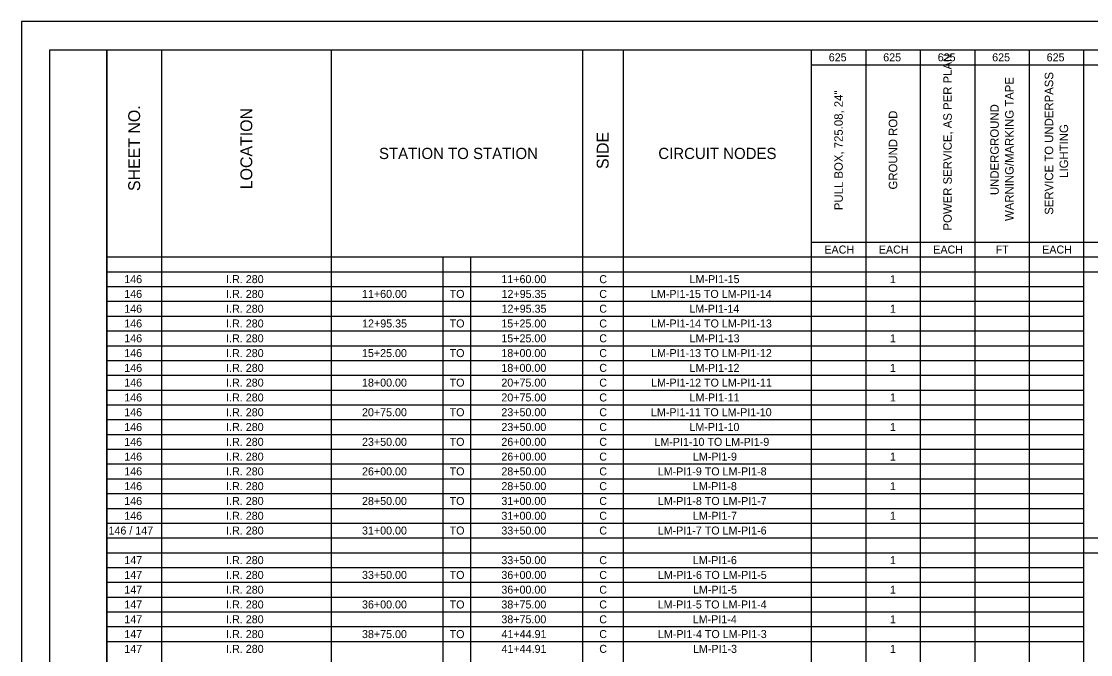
# Model space of a CAD drawing. Extents: x 0 to 34, y 0 to 22.
# Drawn here: x 0 to 18.75, y 10.9 to 22 of the extents above; entities that cross this region are included whole.
import ezdxf

# ---------------------------------------------------------------- set-up
doc = ezdxf.new("R2010")
doc.units = 0
for name, color, linetype in [('Default', 7, 'Continuous'), ('SH_Border', 7, 'Continuous'), ('SH_Cut_Line', 7, 'Continuous')]:
    doc.layers.add(name, color=color, linetype=linetype)

msp = doc.modelspace()

# ---------------------------------------------------------------- linework, layer by layer
at = {"layer": 'Default'}
for p, q in [((1.5, 21.5), (32, 21.5)), ((1.5, 21.5), (1.5, 0.759)), ((2.455, 21.5), (2.455, 0.759)), ((5.434, 21.5), (5.434, 0.759)), ((9.837, 21.5), (9.837, 0.759)), ((10.55, 21.5), (10.55, 0.759)), ((13.852, 21.5), (13.852, 0.5)), ((14.807, 21.5), (14.807, 0.759)), ((15.762, 21.5), (15.762, 0.759)), ((16.718, 21.5), (16.718, 0.759)), ((17.673, 21.5), (17.673, 0.759)), ((18.628, 21.5), (18.628, 0.759)), ((13.852, 21.241), (32, 21.241)), ((13.852, 18.13), (32, 18.13)), ((1.5, 17.87), (32, 17.87)), ((7.393, 17.87), (7.393, 0.759)), ((7.878, 17.87), (7.878, 0.759)), ((1.5, 17.611), (32, 17.611)), ((1.5, 17.352), (18.628, 17.352)), ((1.5, 17.093), (18.628, 17.093)), ((1.5, 16.833), (18.628, 16.833)), ((1.5, 16.574), (18.628, 16.574)), ((1.5, 16.315), (18.628, 16.315)), ((1.5, 16.056), (18.628, 16.056)), ((1.5, 15.796), (18.628, 15.796)), ((1.5, 15.537), (18.628, 15.537)), ((1.5, 15.278), (18.628, 15.278)), ((1.5, 15.019), (18.628, 15.019)), ((1.5, 14.759), (18.628, 14.759)), ((1.5, 14.5), (18.628, 14.5)), ((1.5, 14.241), (18.628, 14.241)), ((1.5, 13.981), (18.628, 13.981)), ((1.5, 13.722), (18.628, 13.722)), ((1.5, 13.463), (18.628, 13.463)), ((1.5, 13.204), (18.628, 13.204)), ((1.5, 12.944), (32, 12.944)), ((1.5, 12.685), (32, 12.685)), ((1.5, 12.426), (18.628, 12.426)), ((1.5, 12.167), (18.628, 12.167)), ((1.5, 11.907), (18.628, 11.907)), ((1.5, 11.648), (18.628, 11.648)), ((1.5, 11.389), (18.628, 11.389)), ((1.5, 11.13), (18.628, 11.13))]:
    msp.add_line(p, q, dxfattribs=at)
at = {"layer": 'SH_Border'}
for points in [[(0.5, 21.5), (1.5, 21.5), (1.5, 0.5), (0.5, 0.5)], [(1.5, 21.5), (33.5, 21.5), (33.5, 0.5), (1.5, 0.5)]]:
    msp.add_lwpolyline(points, close=True, dxfattribs=at)
at = {"layer": 'SH_Cut_Line'}
msp.add_lwpolyline([(0, 0), (34, 0), (34, 22), (0, 22)], close=True, dxfattribs=at)

# ---------------------------------------------------------------- texts
at = {"layer": 'Default'}
for s, height, p in [('625', 0.1403, (14.158, 21.3)), ('625', 0.1403, (15.113, 21.3)), ('625', 0.1403, (16.069, 21.3)), ('625', 0.1403, (17.024, 21.3)), ('625', 0.1403, (17.979, 21.3)), ('STATION TO STATION', 0.19643, (6.271, 19.587)), ('CIRCUIT NODES', 0.19643, (11.169, 19.587)), ('EACH', 0.1403, (14.081, 17.93)), ('EACH', 0.1403, (15.036, 17.93)), ('EACH', 0.1403, (15.991, 17.93)), ('FT', 0.1403, (17.085, 17.93)), ('EACH', 0.1403, (17.901, 17.93)), ('146', 0.1403, (1.804, 17.411)), ('I.R. 280', 0.1403, (3.591, 17.411)), ('11+60.00', 0.1403, (8.417, 17.411)), ('C', 0.14, (10.134, 17.411)), ('LM-PI1-15', 0.1403, (11.718, 17.411)), ('1', 0.14, (15.232, 17.411)), ('146', 0.1403, (1.804, 17.152)), ('I.R. 280', 0.1403, (3.591, 17.152)), ('11+60.00', 0.1403, (5.973, 17.152)), ('TO', 0.1403, (7.51, 17.152)), ('12+95.35', 0.1403, (8.42, 17.152)), ('C', 0.14, (10.134, 17.152)), ('LM-PI1-15 TO LM-PI1-14', 0.14031, (11.04, 17.152)), ('146', 0.1403, (1.804, 16.893)), ('I.R. 280', 0.1403, (3.591, 16.893)), ('12+95.35', 0.1403, (8.42, 16.893)), ('C', 0.14, (10.134, 16.893)), ('LM-PI1-14', 0.1403, (11.714, 16.893)), ('1', 0.14, (15.232, 16.893)), ('146', 0.1403, (1.804, 16.634)), ('I.R. 280', 0.1403, (3.591, 16.634)), ('12+95.35', 0.1403, (5.975, 16.634)), ('TO', 0.1403, (7.51, 16.634)), ('15+25.00', 0.1403, (8.417, 16.634)), ('C', 0.14, (10.134, 16.634)), ('LM-PI1-14 TO LM-PI1-13', 0.14031, (11.043, 16.634)), ('146', 0.1403, (1.804, 16.374)), ('I.R. 280', 0.1403, (3.591, 16.374)), ('15+25.00', 0.1403, (8.417, 16.374)), ('C', 0.14, (10.134, 16.374)), ('LM-PI1-13', 0.1403, (11.718, 16.374)), ('1', 0.14, (15.232, 16.374)), ('146', 0.1403, (1.804, 16.115)), ('I.R. 280', 0.1403, (3.591, 16.115)), ('15+25.00', 0.1403, (5.973, 16.115)), ('TO', 0.1403, (7.51, 16.115)), ('18+00.00', 0.1403, (8.417, 16.115)), ('C', 0.14, (10.134, 16.115)), ('LM-PI1-13 TO LM-PI1-12', 0.14031, (11.043, 16.115)), ('146', 0.1403, (1.804, 15.856)), ('I.R. 280', 0.1403, (3.591, 15.856)), ('18+00.00', 0.1403, (8.417, 15.856)), ('C', 0.14, (10.134, 15.856)), ('LM-PI1-12', 0.1403, (11.717, 15.856)), ('1', 0.14, (15.232, 15.856)), ('146', 0.1403, (1.804, 15.597)), ('I.R. 280', 0.1403, (3.591, 15.597)), ('18+00.00', 0.1403, (5.973, 15.597)), ('TO', 0.1403, (7.51, 15.597)), ('20+75.00', 0.1403, (8.417, 15.597)), ('C', 0.14, (10.134, 15.597)), ('LM-PI1-12 TO LM-PI1-11', 0.14031, (11.043, 15.597)), ('146', 0.1403, (1.804, 15.337)), ('I.R. 280', 0.1403, (3.591, 15.337)), ('20+75.00', 0.1403, (8.417, 15.337)), ('C', 0.14, (10.134, 15.337)), ('LM-PI1-11', 0.1403, (11.717, 15.337)), ('1', 0.14, (15.232, 15.337)), ('146', 0.1403, (1.804, 15.078)), ('I.R. 280', 0.1403, (3.591, 15.078)), ('20+75.00', 0.1403, (5.973, 15.078)), ('TO', 0.1403, (7.51, 15.078)), ('23+50.00', 0.1403, (8.417, 15.078)), ('C', 0.14, (10.134, 15.078)), ('LM-PI1-11 TO LM-PI1-10', 0.14031, (11.04, 15.078)), ('146', 0.1403, (1.804, 14.819)), ('I.R. 280', 0.1403, (3.591, 14.819)), ('23+50.00', 0.1403, (8.417, 14.819)), ('C', 0.14, (10.134, 14.819)), ('LM-PI1-10', 0.1403, (11.715, 14.819)), ('1', 0.14, (15.232, 14.819)), ('146', 0.1403, (1.804, 14.559)), ('I.R. 280', 0.1403, (3.591, 14.559)), ('23+50.00', 0.1403, (5.973, 14.559)), ('TO', 0.1403, (7.51, 14.559)), ('26+00.00', 0.1403, (8.417, 14.559)), ('C', 0.14, (10.134, 14.559)), ('LM-PI1-10 TO LM-PI1-9', 0.14031, (11.102, 14.559)), ('146', 0.1403, (1.804, 14.3)), ('I.R. 280', 0.1403, (3.591, 14.3)), ('26+00.00', 0.1403, (8.417, 14.3)), ('C', 0.14, (10.134, 14.3)), ('LM-PI1-9', 0.1403, (11.776, 14.3)), ('1', 0.14, (15.232, 14.3)), ('146', 0.1403, (1.804, 14.041)), ('I.R. 280', 0.1403, (3.591, 14.041)), ('26+00.00', 0.1403, (5.973, 14.041)), ('TO', 0.1403, (7.51, 14.041)), ('28+50.00', 0.1403, (8.417, 14.041)), ('C', 0.14, (10.134, 14.041)), ('LM-PI1-9 TO LM-PI1-8', 0.14031, (11.16, 14.041)), ('146', 0.1403, (1.804, 13.782)), ('I.R. 280', 0.1403, (3.591, 13.782)), ('28+50.00', 0.1403, (8.417, 13.782)), ('C', 0.14, (10.134, 13.782)), ('LM-PI1-8', 0.1403, (11.775, 13.782)), ('1', 0.14, (15.232, 13.782)), ('146', 0.1403, (1.804, 13.522)), ('I.R. 280', 0.1403, (3.591, 13.522)), ('28+50.00', 0.1403, (5.973, 13.522)), ('TO', 0.1403, (7.51, 13.522)), ('31+00.00', 0.1403, (8.417, 13.522)), ('C', 0.14, (10.134, 13.522)), ('LM-PI1-8 TO LM-PI1-7', 0.14031, (11.161, 13.522)), ('146', 0.1403, (1.804, 13.263)), ('I.R. 280', 0.1403, (3.591, 13.263)), ('31+00.00', 0.1403, (8.417, 13.263)), ('C', 0.14, (10.134, 13.263)), ('LM-PI1-7', 0.1403, (11.776, 13.263)), ('1', 0.14, (15.232, 13.263)), ('146 / 147', 0.1403, (1.528, 13.004)), ('I.R. 280', 0.1403, (3.591, 13.004)), ('31+00.00', 0.1403, (5.973, 13.004)), ('TO', 0.1403, (7.51, 13.004)), ('33+50.00', 0.1403, (8.417, 13.004)), ('C', 0.14, (10.134, 13.004)), ('LM-PI1-7 TO LM-PI1-6', 0.14031, (11.16, 13.004)), ('147', 0.1403, (1.805, 12.485)), ('I.R. 280', 0.1403, (3.591, 12.485)), ('33+50.00', 0.1403, (8.417, 12.485)), ('C', 0.14, (10.134, 12.485)), ('LM-PI1-6', 0.1403, (11.775, 12.485)), ('1', 0.14, (15.232, 12.485)), ('147', 0.1403, (1.805, 12.226)), ('I.R. 280', 0.1403, (3.591, 12.226)), ('33+50.00', 0.1403, (5.973, 12.226)), ('TO', 0.1403, (7.51, 12.226)), ('36+00.00', 0.1403, (8.417, 12.226)), ('C', 0.14, (10.134, 12.226)), ('LM-PI1-6 TO LM-PI1-5', 0.14031, (11.162, 12.226)), ('147', 0.1403, (1.805, 11.967)), ('I.R. 280', 0.1403, (3.591, 11.967)), ('36+00.00', 0.1403, (8.417, 11.967)), ('C', 0.14, (10.134, 11.967)), ('LM-PI1-5', 0.1403, (11.777, 11.967)), ('1', 0.14, (15.232, 11.967)), ('147', 0.1403, (1.805, 11.708)), ('I.R. 280', 0.1403, (3.591, 11.708)), ('36+00.00', 0.1403, (5.973, 11.708)), ('TO', 0.1403, (7.51, 11.708)), ('38+75.00', 0.1403, (8.417, 11.708)), ('C', 0.14, (10.134, 11.708)), ('LM-PI1-5 TO LM-PI1-4', 0.14031, (11.159, 11.708)), ('147', 0.1403, (1.805, 11.448)), ('I.R. 280', 0.1403, (3.591, 11.448)), ('38+75.00', 0.1403, (8.417, 11.448)), ('C', 0.14, (10.134, 11.448)), ('LM-PI1-4', 0.1403, (11.774, 11.448)), ('1', 0.14, (15.232, 11.448)), ('147', 0.1403, (1.805, 11.189)), ('I.R. 280', 0.1403, (3.591, 11.189)), ('38+75.00', 0.1403, (5.973, 11.189)), ('TO', 0.1403, (7.51, 11.189)), ('41+44.91', 0.1403, (8.42, 11.189)), ('C', 0.14, (10.134, 11.189)), ('LM-PI1-4 TO LM-PI1-3', 0.14031, (11.162, 11.189)), ('147', 0.1403, (1.805, 10.93)), ('I.R. 280', 0.1403, (3.591, 10.93)), ('41+44.91', 0.1403, (8.42, 10.93)), ('C', 0.14, (10.134, 10.93)), ('LM-PI1-3', 0.1403, (11.777, 10.93)), ('1', 0.14, (15.232, 10.93))]:
    msp.add_text(s, height=height, dxfattribs=at).set_placement(p)
for s, height, p in [('POWER SERVICE, AS PER PLAN', 0.14894, (16.315, 18.334)), ('WARNING/MARKING TAPE', 0.14894, (17.4, 18.501)), ('SERVICE TO UNDERPASS ', 0.14894, (18.094, 18.61)), ('PULL BOX, 725.08, 24"', 0.14894, (14.404, 18.691)), ('SHEET NO.', 0.2085, (2.082, 19.026)), ('LOCATION', 0.2085, (4.049, 19.057)), ('UNDERGROUND ', 0.14894, (17.139, 18.955)), ('GROUND ROD', 0.1489, (15.359, 19.053)), ('LIGHTING', 0.1489, (18.355, 19.257)), ('SIDE', 0.2085, (10.298, 19.412))]:
    msp.add_text(s, height=height, rotation=90, dxfattribs=at).set_placement(p)

doc.saveas('drawing.dxf')
